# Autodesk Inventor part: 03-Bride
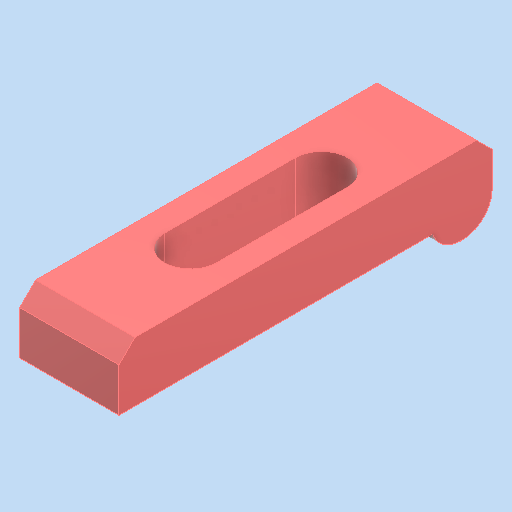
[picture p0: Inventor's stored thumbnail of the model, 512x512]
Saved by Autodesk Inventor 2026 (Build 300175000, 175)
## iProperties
Created: 2025-12
Part Number: 03-Bride
Material: Générique
Document SubType Name: Modeling
Designer: thierry.jost
Density: 1 g/cm^3
Appearance: Lisse - Rouge
Author: thierry.jost
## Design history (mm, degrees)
sketch "Esquisse1"
  geometry: L1 (16.079, 40.445)-(16.079, -53.555); L2 (16.079, -53.555)-(-3.921, -53.555); L3 (-3.921, -53.555)-(-3.921, -38.555); L4 (-3.921, -38.555)-(1.079, -38.555); L5 (1.079, -38.555)-(1.079, 40.445); L6 (1.079, 40.445)-(16.079, 40.445); 1 further point
  constraints: 12 end point, 5 perpendicular, 1 vertical
  dimensions: "d0" = 94 distance of L1.start L1.end; "d2" = 15 distance of L2.end L3.end; "d3" = 20 distance of L1.end L2.end; "d4" = 15 distance of L5.end L1.start
extrude "Extrusion1" new body sketch "Esquisse1" distance "d5" = 25; taper "d6" = 0 deg
sketch "Esquisse2"
  geometry: L1 (19, 30.5)-(19, 63.5); L2 (6, 63.5)-(6, 30.5); L3 (0, 94)-(25, 94) reference; L4 (0, 94)-(0, 0) reference; L5 (25, 94)-(25, 0) reference; A1 r 6.5 centre (12.5, 30.5) between (6, 30.5) and (19, 30.5); A2 r 6.5 centre (12.5, 63.5) between (19, 63.5) and (6, 63.5); 2 further points
  constraints: 4 end point, 4 point on circle, 2 centre point, 2 parallel, 2 tangent, 1 midpoint
  dimensions: "d7" = 6.5 radius of A1 (= d9); "d8" = 33 distance of A2.centre A1.centre; "d9" = 6.5 radius of A2; "d10" = 47 distance from line of L3 point (6, 47); "d11" = 12.5 distance from line of L4 A2.centre; "d18" = 12.5 distance from line of A1.centre L4 (= d11)
extrude "Extrusion2" cut sketch "Esquisse2" extent not by distance; stored distance "d12" = 0; taper "d13" = 0 deg
fillet "Congé1" dims "d14" = 7.5
chamfer "Chanfrein1" distance "d15" = 4; stored, may be unused: second distance "d16" = 2, angle "d17" = 45 deg
node "Solide1"
